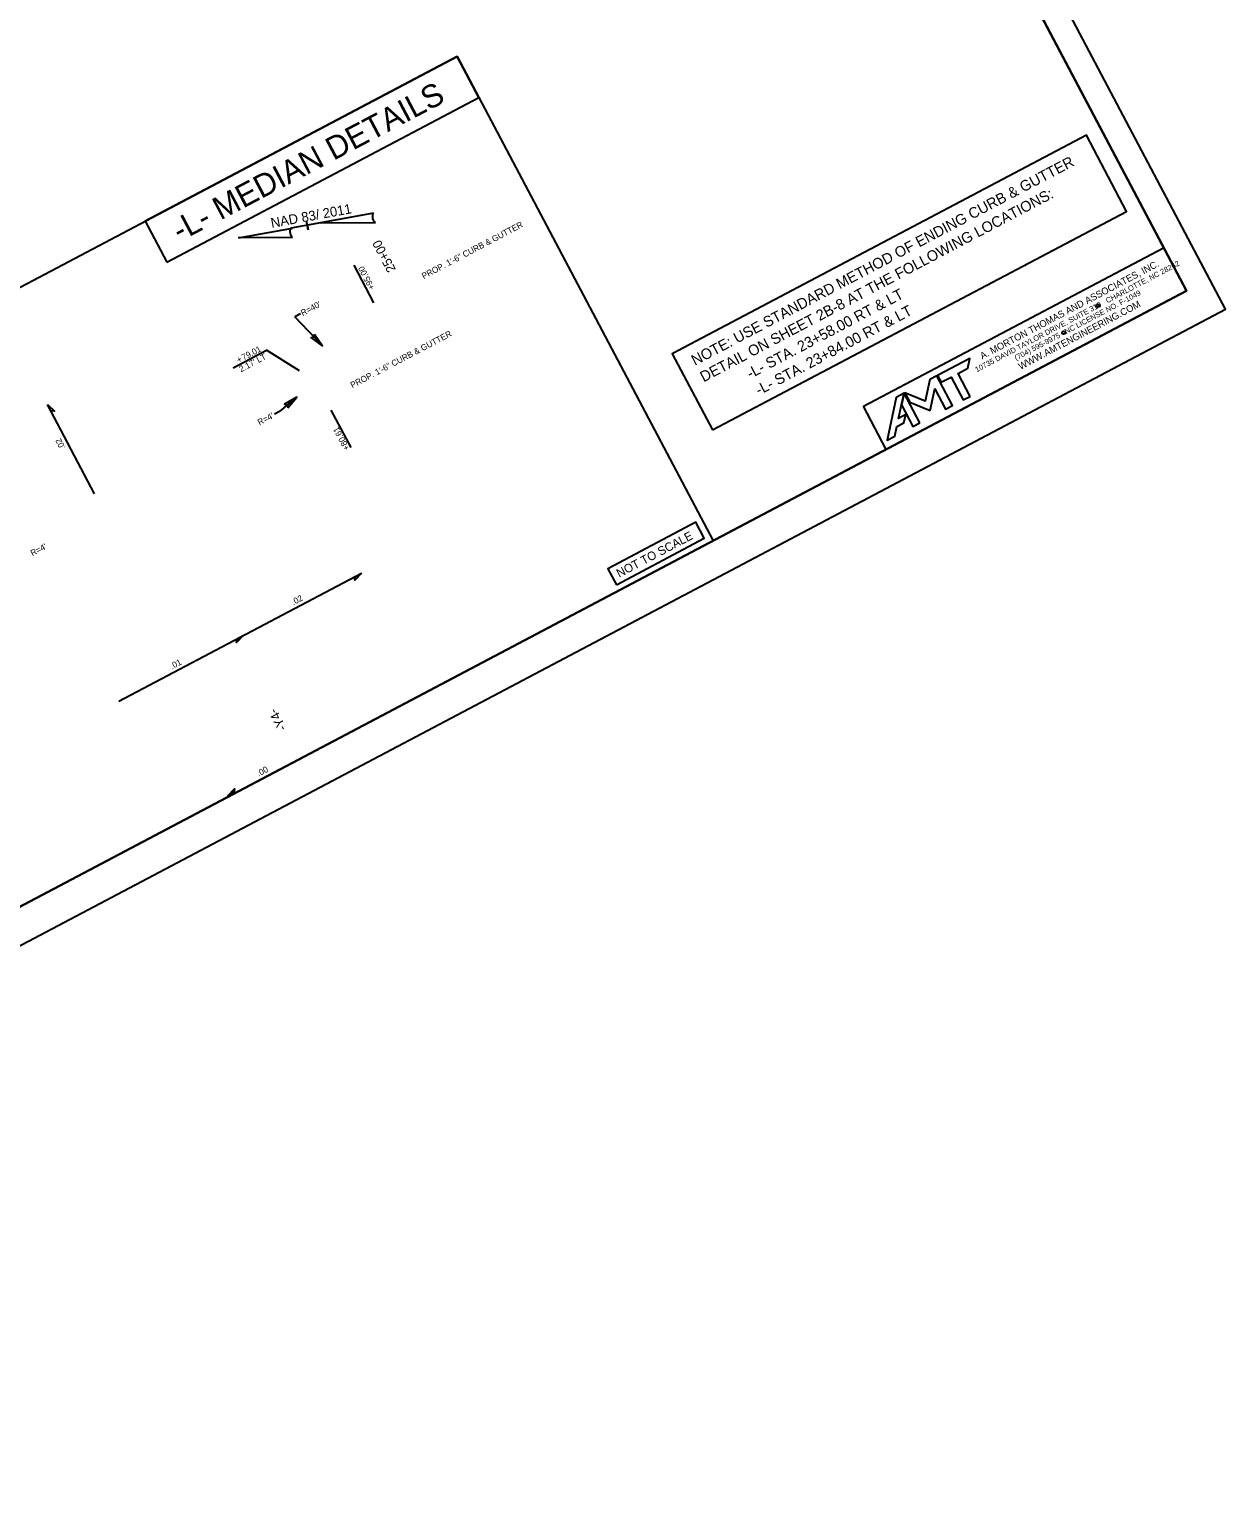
# Model space of a CAD drawing. Extents: x 1487555 to 1489555, y 497613 to 499367.
# Drawn here: x 1488773 to 1489555, y 497613 to 498582 of the extents above; entities that cross this region are included whole.
import ezdxf

# ---------------------------------------------------------------- set-up
doc = ezdxf.new("R2010")
doc.units = 0
for name, color, linetype in [('Prop Dimension', 7, 'Continuous'), ('Prop Dimension Text', 7, 'Continuous'), ('Prop Grid Mask', 7, 'Continuous'), ('Prop Horizontal Alignment Curve and Spiral Data', 7, 'Continuous'), ('Prop Horizontal Alignment Direction Label', 7, 'Continuous'), ('Prop North Arrow NAD83 for Plan Sheets CELL', 7, 'Continuous'), ('Prop Superelevation  Arrow CELL', 7, 'Continuous'), ('Prop Superelevation Label', 7, 'Continuous'), ('Prop Terminator CELL', 7, 'Continuous'), ('Sheet Block Title CELL', 7, 'Continuous'), ('Sheet Plan CELL', 7, 'Continuous'), ('Sheet Plot Border Outside CELL', 7, 'Continuous')]:
    doc.layers.add(name, color=color, linetype=linetype)

msp = doc.modelspace()

# ---------------------------------------------------------------- linework, layer by layer
at = {"layer": 'Prop Dimension'}
for p, q in [((1488997.88, 498402.97), (1488984.92, 498427.52)), ((1488949.7, 498395.66), (1488946.17, 498393.8)), ((1488964.12, 498374.83), (1488946.17, 498393.8)), ((1488905.7, 498360.36), (1488927.6, 498371.93)), ((1488949.07, 498358.46), (1488927.6, 498371.93)), ((1488936.42, 498331.95), (1488947.33, 498341.19)), ((1488982.86, 498308.16), (1488969.89, 498332.72)), ((1488936.42, 498331.95), (1488932.88, 498330.09))]:
    msp.add_line(p, q, dxfattribs=at)
at = {"layer": 'Prop Grid Mask'}
for points in [[(1488862.31, 498429.5), (1489066.5, 498537.32), (1489052.32, 498564.17), (1488848.13, 498456.35)], [(1489219.35, 498319.7), (1489490.26, 498462.75), (1489463.9, 498512.66), (1489193, 498369.61)], [(1489318.05, 498335.29), (1489514.4, 498438.97), (1489529.32, 498410.71), (1489332.97, 498307.04)], [(1489156.43, 498218.45), (1489213.96, 498248.83), (1489208.44, 498259.29), (1489150.91, 498228.91)]]:
    msp.add_lwpolyline(points, close=True, dxfattribs=at)
at = {"layer": 'Prop North Arrow NAD83 for Plan Sheets CELL'}
for p, q in [((1488997.54, 498461.62), (1488962.84, 498455.22)), ((1488909.28, 498445.4), (1488944.54, 498451.87)), ((1488962.84, 498455.22), (1488943.51, 498451.68)), ((1488944.54, 498451.87), (1488943.54, 498451.68)), ((1488954.81, 498450.74), (1488953.73, 498456.64)), ((1488954.34, 498453.32), (1488954.82, 498450.7)), ((1488954.82, 498450.7), (1488954.83, 498450.66)), ((1488962.84, 498455.22), (1488998.82, 498455.46)), ((1488909.28, 498445.4), (1488909.29, 498445.36)), ((1488909.28, 498445.4), (1488909.29, 498445.36)), ((1488944.59, 498445.58), (1488909.29, 498445.36))]:
    msp.add_line(p, q, dxfattribs=at)
for centre, start_param, end_param in [((1488998.37, 498458.6), 0.201328, 3.141593), ((1488944.39, 498448.7), 0.216388, 2.908219)]:
    msp.add_ellipse(centre, major_axis=(-0.55, 3.12), ratio=0.461098, start_param=start_param, end_param=end_param, dxfattribs=at)
at = {"layer": 'Prop Superelevation  Arrow CELL'}
msp.add_line((1488815.12, 498277.93), (1488784.3, 498336.29), dxfattribs=at)
for points in [[(1488784.3, 498336.29), (1488788.87, 498331.92), (1488786.46, 498332.2)], [(1488989.63, 498226.01), (1488985.25, 498221.44), (1488985.54, 498223.85)], [(1488912.4, 498185.23), (1488908.02, 498180.66), (1488908.31, 498183.07)], [(1488902.2, 498080.33), (1488906.57, 498084.9), (1488906.29, 498082.49)]]:
    msp.add_lwpolyline(points, close=True, dxfattribs=at)
at = {"layer": 'Prop Superelevation Label'}
msp.add_line((1488831.04, 498142.28), (1488989.63, 498226.01), dxfattribs=at)
at = {"layer": 'Prop Terminator CELL'}
for points in [[(1488959.06, 498382.43), (1488964.12, 498374.83), (1488956.74, 498380.3), (1488958.69, 498380.56)], [(1488941.46, 498334.19), (1488947.33, 498341.19), (1488939.39, 498336.57), (1488941.3, 498336.09)]]:
    msp.add_lwpolyline(points, close=True, dxfattribs=at)
at = {"layer": 'Sheet Block Title CELL'}
msp.add_lwpolyline([(1489318.05, 498335.29), (1489514.4, 498438.97), (1489529.32, 498410.71), (1489332.97, 498307.04)], close=True, dxfattribs=at)
for points in [[(1489387.85, 498341.72), (1489379.95, 498356.68), (1489386.4, 498360.08), (1489387.77, 498366.5), (1489366.64, 498355.35), (1489368.99, 498350.89), (1489375.5, 498354.33), (1489383.4, 498339.36), (1489387.85, 498341.72)], [(1489361.82, 498332.35), (1489364.87, 498346.53), (1489371.87, 498333.28), (1489376.32, 498335.63), (1489366.07, 498355.05), (1489361.62, 498352.69), (1489358.49, 498338.65), (1489345.22, 498344.03), (1489348.48, 498337.85), (1489361.82, 498332.35)], [(1489342.95, 498336.16), (1489344.65, 498343.73), (1489339.45, 498340.99), (1489333.58, 498313.06), (1489338.62, 498315.72), (1489339.93, 498321.99), (1489344.54, 498324.43), (1489345.78, 498329.77), (1489341, 498327.25), (1489342.95, 498336.16)], [(1489354.9, 498324.32), (1489344.65, 498343.73), (1489342.95, 498336.16), (1489350.45, 498321.97), (1489354.9, 498324.32)]]:
    msp.add_lwpolyline(points, dxfattribs=at)
for centre in [(1489471.31, 498401.03), (1489449.07, 498383.38)]:
    msp.add_circle(centre, 1, dxfattribs=at)
at = {"layer": 'Sheet Plan CELL'}
for points in [[(1489039.06, 499339.23), (1487712.59, 498638.82), (1488202.86, 497710.31), (1489529.32, 498410.71)], [(1488202.86, 497710.31), (1487712.58, 498638.79), (1488862.13, 499245.82), (1488932.21, 499113.13), (1489109.11, 499206.52), (1489529.32, 498410.71)], [(1488035.48, 498027.26), (1489052.32, 498564.17), (1489219.68, 498247.22), (1488202.84, 497710.3)]]:
    msp.add_lwpolyline(points, close=True, dxfattribs=at)
at = {"layer": 'Sheet Plot Border Outside CELL'}
msp.add_lwpolyline([(1488066.15, 497612.67), (1489554.86, 498398.74), (1489043.57, 499367.04), (1487554.86, 498580.97)], close=True, dxfattribs=at)

# ---------------------------------------------------------------- texts
at = {"layer": 'Prop Dimension Text'}
for s, rotation, p in [('PROP. 1\'-6" CURB & GUTTER', 27.83509, (1489030.4, 498418.33)), ('+95.00', 117.83509, (1488998.56, 498412.76)), ("R=40'", 27.83509, (1488951.26, 498394.22)), ('PROP. 1\'-6" CURB & GUTTER', 27.83509, (1488983.78, 498346.93)), ('79.01', 27.83509, (1488912.67, 498365.18)), ('+', 27.83509, (1488909.33, 498363.41)), ("2.17' LT", 27.83509, (1488910.91, 498357.46)), ("R=4'", 27.83509, (1488923.02, 498322.62)), ('+80.61', 117.83509, (1488982.1, 498307.59)), ("R=4'", 27.83509, (1488774.5, 498237.02))]:
    msp.add_text(s, height=4, rotation=rotation, dxfattribs=at).set_placement(p)
at = {"layer": 'Prop Horizontal Alignment Curve and Spiral Data'}
for s, height, p in [('-L- MEDIAN DETAILS', 15, (1488870.87, 498442.71)), ('NOTE: USE STANDARD METHOD OF ENDING CURB & GUTTER', 7, (1489207.82, 498361.66)), ('DETAIL ON SHEET 2B-8 AT THE FOLLOWING LOCATIONS:', 7, (1489213.54, 498350.83)), ('-L- STA. 23+58.00 RT & LT', 7, (1489244.02, 498353.07)), ('-L- STA. 23+84.00 RT & LT', 7, (1489249.74, 498342.23)), ('NOT TO SCALE', 5.625, (1489158.33, 498222.96))]:
    msp.add_text(s, height=height, rotation=27.83509, dxfattribs=at).set_placement(p)
at = {"layer": 'Prop Horizontal Alignment Direction Label'}
for s, p in [('25+00', (1489012.37, 498424.79)), ('-Y4-', (1488940.9, 498124.68))]:
    msp.add_text(s, height=6, rotation=117.83509, dxfattribs=at).set_placement(p)
at = {"layer": 'Prop North Arrow NAD83 for Plan Sheets CELL'}
msp.add_text('NAD 83/ 2011', height=6.375, rotation=10.39314, dxfattribs=at).set_placement((1488930.99, 498451.93))
at = {"layer": 'Prop Superelevation Label'}
for s, rotation, p in [('.02', 117.89497, (1488796.22, 498308.12)), ('.02', 27.83509, (1488945.21, 498204.96)), ('.01', 27.83509, (1488865.86, 498163.06)), ('.00', 27.83509, (1488922.54, 498092.86))]:
    msp.add_text(s, height=4, rotation=rotation, dxfattribs=at).set_placement(p)
at = {"layer": 'Sheet Block Title CELL'}
for s, height, p in [('A. MORTON THOMAS AND ASSOCIATES, INC.', 4.5, (1489395.82, 498365.78)), ('10735 DAVID TAYLOR DRIVE, SUITE 310   CHARLOTTE, NC 28262', 3.5, (1489392.23, 498357.38)), ('(704) 595-9975   NC LICENSE NO. F-1049', 3.5, (1489418.01, 498365.06)), ('WWW.AMTENGINEERING.COM', 4.5, (1489420.93, 498358.97))]:
    msp.add_text(s, height=height, rotation=27.83461, dxfattribs=at).set_placement(p)

doc.saveas('drawing.dxf')
